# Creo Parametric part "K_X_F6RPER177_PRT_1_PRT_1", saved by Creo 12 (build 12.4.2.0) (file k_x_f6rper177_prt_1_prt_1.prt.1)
Units: Custom; MM, KILOGRAM, SECS

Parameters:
  PTC_WM_ITERATION = "0"
  PTC_WM_VERSION = "-.0"
  PTC_WM_LIFECYCLE_STATE = "In Work"
  PTC_WM_LIFECYCLE = "MO_CADDocument"
  PTC_WM_CREATED_BY = "Maximilian Roepper (Z0017RMS: MO)"
  PTC_WM_CREATED_ON = "18-Sep-26 11:36:42 AM"
  PTC_WM_MODIFIED_BY = "Maximilian Roepper (Z0017RMS: MO)"
  PTC_WM_MODIFIED_ON = "18-Sep-26 11:36:46 AM"
  PDMLINKNUMBER = "PDM000071454758"
  PTC_WM_NAME = "k_x_f6rper177_prt_1_prt_1.prt"
  PTC_WM_NUMBER = "PDM000071454758"

Other parameters: WEIGHT, WEIGHT_FACTOR, WEIGHT_ADD, _MASS_TEMP, _DIFF_TEMP, MC_ERRORS, SUPPLIER

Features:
  1. coordinate system
  2. datum plane "PRT_YZ"
  3. datum plane "PRT_XY"
  4. datum plane "PRT_XZ"
  5. coordinate system
  6. datum axis
  7. datum axis
  8. datum axis
  9. coordinate system
  10. imported feature
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
Other named items: PRT, SIEMENS_MO, DRW_VIEW_ORG, PRT_X, PRT_Y, PRT_Z, CS0, ROUGH_GROB

Layers: 00_STD_CSYS-KSYS, 01_STD_PLANES-EBENEN, 02_STD_AXES-ACHSEN, 03_STD_CSYS-KSYS, 24_IMPORT_FEAT-IMPORT_KE

Surfaces: 27 tabulated cylinder, 5 plane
